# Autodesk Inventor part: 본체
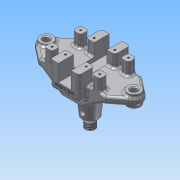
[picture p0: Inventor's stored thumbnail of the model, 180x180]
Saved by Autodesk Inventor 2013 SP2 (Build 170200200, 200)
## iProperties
Created: 2025-07
Part Number: 본체
Material: 알루미늄 6061
Document SubType Name: Modeling
Designer: a
Density: 2.71 g/cm^3
Mass: 328.838 g
Surface Area: 260.966 cm^2
Volume: 121.342 cm^3
Author: a
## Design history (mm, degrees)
sketch "스케치1"
  geometry: L1 (65, 23)-(-65, 23); L2 (-65, 23)-(-65, -23); L3 (-65, -23)-(65, -23); L4 (65, -23)-(65, 23); L5 (65, 23)-(-65, -23); L6 (-65, 23)-(65, -23); L7 (61.157, 7.88)-(41.804, 23); L8 (-61.157, 7.88)-(-41.804, 23); L9 (-61.157, -7.88)-(-41.804, -23); L10 (61.157, -7.88)-(41.804, -23); L11 (65, 0)-(-65, 0); A1 r 10 centre (55, 0) between (65, 0) and (61.157, 7.88); A2 r 10 centre (-55, 0) between (-65, 0) and (-61.157, 7.88); 3 further points
  constraints: 22 end point, 6 midpoint, 6 point on circle, 4 point on line, 4 tangent, 2 centre point, 2 horizontal alignment, 2 parallel, 2 perpendicular, 1 horizontal
  dimensions: "d0" = 130 distance of L2.end L3.end; "d2" = 46 distance of L3.end L1.start; "d3" = 20 diameter of A1; "d4" = 20 diameter of A2; "d6" = 38 deg angle of L11 L10; "d7" = 38 deg angle of L7 L11; "d8" = 38 deg angle of L11 L8; "d9" = 38 deg angle of L11 L9; "d10" = 130 distance of L11.start L11.end
extrude "돌출1" new body sketch "스케치1" distance "d11" = 9; taper "d12" = 0 deg
sketch "스케치2"
  geometry: L1 (-65, 0)-(-65, 9) reference; L2 (-65, 9)-(65, 9) reference; L3 (65, 9)-(65, 0) reference; L4 (65, 0)-(-65, 0) reference; L5 (16, -16)-(-16, -16); L6 (16, -16)-(38.85, 0); L7 (-16, -16)-(-38.85, 0); L8 (38.85, 0)-(-38.85, 0); 3 further points
  constraints: 8 end point, 2 midpoint, 2 parallel, 2 point on line, 1 vertical alignment
  dimensions: "d13" = 32 distance of L5.start L5.end; "d15" = 35 deg angle of L5 L6; "d17" = 35 deg angle of L7 L5; "d19" = 16 distance between parallel lines of L4 L5
extrude "돌출2" join sketch "스케치2" stored distance "d20" = 46; taper "d21" = 0 deg
sketch "스케치3"
  geometry: L1 (-18, -13)-(18, -13); L2 (18, -13)-(18, -32); L3 (18, -32)-(-18, -32); L4 (-18, -32)-(-18, -13); L5 (-18, 32)-(18, 32); L6 (18, 32)-(18, 13); L7 (18, 13)-(-18, 13); L8 (-18, 13)-(-18, 32); 3 further points
  constraints: 16 end point, 4 parallel, 2 horizontal, 2 midpoint, 2 perpendicular, 2 vertical alignment
  dimensions: "d22" = 36 distance of L2.end L3.end; "d24" = 36 distance of L5.start L5.end; "d25" = 64 distance between parallel lines of L3 L5; "d26" = 32 distance from line of point (0, 0) L5; "d27" = 26 distance between parallel lines of L1 L7; "d28" = 13 distance from line of point (0, 0) L7
extrude "돌출3" join sketch "스케치3" distance "d29" = 16; taper "d31" = 0 deg; dims "d30" = 15, "d32" = 0
sketch "스케치4"
  geometry: L1 (-35, 13)-(-25, 13); L2 (-25, 13)-(-25, 23); L3 (-25, 23)-(-35, 23); L4 (-35, 23)-(-35, 13); L5 (-35, 13)-(-25, 23); L6 (-25, 13)-(-35, 23); 2 further points
  constraints: 12 end point, 2 midpoint, 2 parallel, 1 horizontal, 1 perpendicular
  dimensions: "d33" = 10 distance of L2.end L3.end; "d35" = 10 distance of L3.end L1.start; "d36" = 30 horizontal distance of point (0, 0) point (-30, 18); "d37" = 18 vertical distance of point (0, 0) point (-30, 18)
extrude "돌출4" join sketch "스케치4" distance "d38" = 16; taper "d39" = 0 deg
sketch "스케치5"
  geometry: L1 (0, 0)-(36, 0) reference; L2 (10, 0)-(26, 0); L3 (26, 0)-(26, -21); L4 (26, -21)-(10, -21); L5 (10, -21)-(10, 0); 2 further points
  constraints: 8 end point, 2 parallel, 1 collinear, 1 horizontal, 1 midpoint, 1 perpendicular, 1 vertical alignment
  dimensions: "d46" = 16 distance of L2.start L2.end; "d48" = 21 distance of L2.end L3.end
extrude "돌출5" cut sketch "스케치5" stored distance "d49" = 16; taper "d50" = 0 deg
sketch "스케치6"
  geometry: C1 r 8 at (-55, 0); A1 r 10 centre (-55, 0) between (-61.157, 7.88) and (-61.157, -7.88) reference; 1 further point
  constraints: 1 centre point, 1 coincident
  dimensions: "d51" = 16 diameter of C1
extrude "돌출6" join sketch "스케치6" distance "d52" = 3; taper "d53" = 0 deg
sketch "스케치7"
  geometry: C1 r 8 at (-55, 0); A1 r 10 centre (-55, 0) between (-61.157, 7.88) and (-61.157, -7.88) reference; 1 further point
  constraints: 1 centre point, 1 coincident
  dimensions: "d54" = 16 diameter of C1
extrude "돌출7" join sketch "스케치7" distance "d55" = 3; taper "d56" = 0 deg
sketch "스케치8"
  geometry: L1 (38.85, 0)-(16, -16) reference; L2 (16, -16)-(-16, -16) reference; L3 (-16, -16)-(-38.85, 0) reference; L4 (-38.85, 0)-(-47, 0) reference; L5 (-47, 0)-(-47, -3) reference; L6 (-47, -3)-(-63, -3) reference; L7 (-63, -3)-(-63, 0) reference; L8 (-63, 0)-(-65, 0) reference; L9 (-65, 0)-(-65, 9) reference; L10 (-65, 9)-(-63, 9) reference; L11 (-63, 9)-(-63, 12) reference; L12 (-63, 12)-(-47, 12) reference; L13 (-47, 12)-(-47, 9) reference; L14 (-47, 9)-(-8, 9) reference; L15 (-8, 9)-(-8, 4) reference; L16 (-8, 4)-(8, 4) reference; L17 (8, 4)-(8, 9) reference; L18 (8, 9)-(47, 9) reference; L19 (47, 9)-(47, 12) reference; L20 (47, 12)-(63, 12) reference; L21 (63, 12)-(63, 9) reference; L22 (63, 9)-(65, 9) reference; L23 (65, 9)-(65, 0) reference; L24 (65, 0)-(63, 0) reference; L25 (63, 0)-(63, -3) reference; L26 (63, -3)-(47, -3) reference; L27 (47, -3)-(47, 0) reference; L28 (47, 0)-(38.85, 0) reference; L29 (0, -16)-(0, -57); L30 (-12.5, -16)-(-12.5, -20); L31 (-12.5, -20)-(-10, -43); L32 (-10, -43)-(-4.7, -43); L33 (-4.7, -43)-(-4.7, -46); L34 (-4.7, -57)-(0, -57); L35 (-12.5, -16)-(0, -16); L36 (-6, -48.252)-(-6, -56.249); L37 (-4.7, -46)-(-6, -48.252); L38 (-4.7, -57)-(-6, -56.249); 1 further point
  constraints: 20 end point, 5 perpendicular, 3 parallel, 1 midpoint, 1 point on line
  dimensions: "d57" = 41 distance of L29.start L29.end; "d59" = 4 distance of L30.start L30.end; "d60" = 23 vertical distance of L31.end L30.end; "d61" = 3 distance of L32.end L33.end; "d62" = 25 diameter of L30 L29; "d63" = 20 diameter of L31.end L29; "d65" = 9.4 diameter of L33 L29; "d66" = 9.4 diameter of L34.start L29; "d130" = 30 deg angle of L36 L37; "d131" = 12 diameter of L36 L29
revolve "회전1" sketch "스케치8" stored, may be unused: angle "d67" = 90 deg
sketch "스케치9"
  geometry: L1 (-6, 23)-(-6, 32) reference; L2 (-6, 32)-(4, 32) reference; L3 (4, 32)-(4, -32) reference; L4 (4, -32)-(-6, -32) reference; L5 (-6, -32)-(-6, -23) reference; L6 (-6, -23)-(-16, -23) reference; L7 (-16, -23)-(-16, -12.5) reference; L8 (-16, -12.5)-(-20, -12.5) reference; L9 (-20, -12.5)-(-43, -10) reference; L10 (-43, -10)-(-43, -4.7) reference; L11 (-43, -4.7)-(-46, -4.7) reference; L12 (-57, -4.7)-(-57, 4.7) reference; L13 (-46, 4.7)-(-43, 4.7) reference; L14 (-43, 4.7)-(-43, 10) reference; L15 (-43, 10)-(-20, 12.5) reference; L16 (-20, 12.5)-(-16, 12.5) reference; L17 (-16, 12.5)-(-16, 23) reference; L18 (-16, 23)-(-6, 23) reference; L19 (-26.597, 11.783)-(-26.164, 7.806); L20 (-26.164, 7.806)-(-35.112, 6.834); L21 (-35.112, 6.834)-(-35.544, 10.81); L22 (-26.597, 11.783)-(-35.544, 10.81); L23 (-46, -4.7)-(-48.252, -6) reference; L24 (-48.252, -6)-(-56.249, -6) reference; L25 (-56.249, -6)-(-57, -4.7) reference; L26 (-57, 4.7)-(-56.249, 6) reference; L27 (-56.249, 6)-(-48.252, 6) reference; L28 (-48.252, 6)-(-46, 4.7) reference; 1 further point
  constraints: 8 end point, 4 perpendicular, 2 point on line
  dimensions: "d68" = 9 distance between parallel lines of L21 L19; "d70" = 7.5 distance from line of L21 L14.end; "d71" = 4 distance between parallel lines of L22 L20
extrude "돌출8" cut sketch "스케치9" stored distance "d72" = 7; taper "d73" = 0 deg
sketch "스케치10"
  geometry: L1 (7, 0)-(0, 0) reference; L2 (0, 0)-(0, -9) reference; L3 (7, -9)-(0, -9) reference; C1 r 3.5 at (3.5, 0); 2 further points
  constraints: 2 midpoint, 1 centre point, 1 horizontal alignment, 1 tangent, 2 other
extrude "돌출9" cut sketch "스케치10" distance "d74" = 4; taper "d75" = 0 deg
sketch "스케치11"
  geometry: C1 r 8 at (0, 0) reference; C2 r 4 at (0, 0); 1 further point
  constraints: 1 centre point, 1 coincident
  dimensions: "d76" = 8 diameter of C2
extrude "돌출10" cut sketch "스케치11" stored distance "d77" = 4; taper "d78" = 0 deg
sketch "스케치12"
  geometry: 2 further points
  dimensions: "d79" = 30 horizontal distance of point (0, 0) point (-30, 18); "d80" = 18 vertical distance of point (0, 0) point (-30, 18)
hole "구멍1" sketch "스케치12" at (-30, 18) diameter "d81" = 2.459; stored, may be unused: countersink angle "d85" = 90 deg, drill point angle "d87" = 118 deg; dims "d82" = 6, "d83" = 4, "d84" = 2, "d86" = 8
sketch "스케치13"
  geometry: 2 further points
  dimensions: "d94" = 13 horizontal distance of point (0, 0) point (-13, 18); "d95" = 18 vertical distance of point (0, 0) point (-13, 18)
hole "구멍2" sketch "스케치13" at (-13, 18) diameter "d96" = 2.459; stored, may be unused: countersink angle "d100" = 90 deg, drill point angle "d102" = 118 deg; dims "d97" = 6, "d98" = 4, "d99" = 2, "d101" = 8
fillet "모깎기1" dims "d109" = 3
fillet "모깎기2" dims "d110" = 3
fillet "모깎기3" dims "d111" = 3
fillet "모깎기4" dims "d112" = 3
fillet "모깎기5" dims "d113" = 3
fillet "모깎기6" dims "d114" = 3
fillet "모깎기8" dims "d116" = 3
fillet "모깎기9" dims "d117" = 3
fillet "모깎기10" dims "d118" = 3
fillet "모깎기12" dims "d120" = 3
fillet "모깎기13" dims "d121" = 3
fillet "모깎기14" dims "d122" = 3
fillet "모깎기15" dims "d123" = 3
chamfer "모따기1" distance "d124" = 1; stored, may be unused: second distance "d125" = 2, angle "d126" = 45 deg
sketch "스케치14"
  geometry: 3 further points
  constraints: 1 vertical alignment, 1 other
  dimensions: "d127" = 24 vertical distance of point (0, 21) point (8, -3)
feature "엠보싱1" sketch "스케치14" dims "d128" = 0.5, "d129" = 0
feature "스레드1" dims "d132" = 10, "d133" = 0
node "솔리드1"
pattern_linear "직사각형 패턴1" dims "d42" = 60, "d45" = 36
mirror "대칭1"
mirror "대칭2"
pattern_linear "직사각형 패턴2" dims "d90" = 60, "d93" = 36
pattern_linear "직사각형 패턴3" dims "d105" = 26, "d108" = 36
node "절단 모서리 투영1"
node "절단 모서리 투영2"
node "절단 모서리 투영3"
